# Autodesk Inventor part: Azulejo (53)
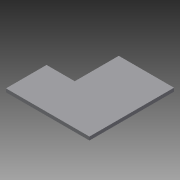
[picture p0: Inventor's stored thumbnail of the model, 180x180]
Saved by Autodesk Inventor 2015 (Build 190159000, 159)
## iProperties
Created: 2015-04
Part Number: Azulejo (53)
Material: Genérico
Document SubType Name: Modeling
Designer: Felipe
Density: 1 g/cm^3
Appearance: Padrão
Author: Felipe
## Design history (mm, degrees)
sketch "Sketch2"
  geometry: L1 (147.415, 811.071)-(147.415, 91.071); L2 (1627.415, 91.071)-(1627.415, 1591.071); L3 (147.415, 91.071)-(1627.415, 91.071); L4 (647.415, 1591.071)-(647.415, 811.071); L5 (647.415, 811.071)-(147.415, 811.071); L6 (147.415, 1591.071)-(1627.415, 1591.071); L7 (1627.415, 1591.071)-(1627.415, 1651.071); L8 (1627.415, 1651.071)-(147.415, 1651.071); L9 (147.415, 1651.071)-(147.415, 1591.071); 1 further point
  constraints: 18 end point, 1 point on line
extrude "Extrusion2" new body sketch "Sketch2" distance "d2" = 60; taper "d3" = 0 deg
body "Solid2"
